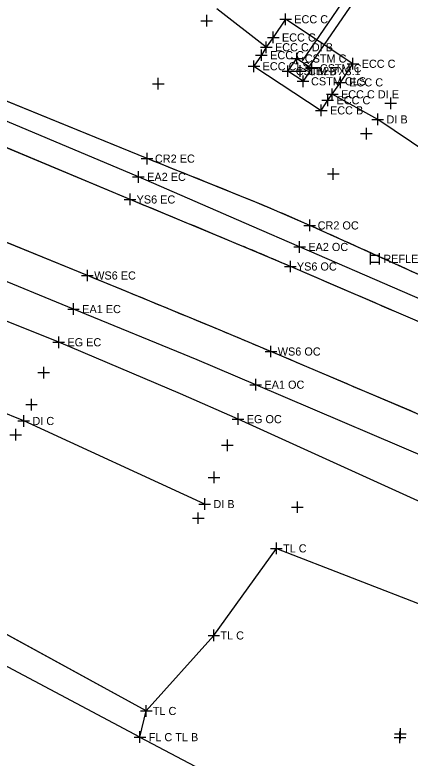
# Model space of a CAD drawing. Extents: x 1324236 to 1326110, y 459090 to 460782.
# Drawn here: x 1325338.7 to 1325406.7, y 459650.5 to 459778.5 of the extents above; entities that cross this region are included whole.
import ezdxf

# ---------------------------------------------------------------- set-up
doc = ezdxf.new("R2010")
doc.units = 0
for name, color, linetype in [('DR_X_Ditch', 7, 'Continuous'), ('DR_X_Drive_Pipe', 7, 'Continuous'), ('DR_X_Paved_Gutter', 7, 'Continuous'), ('DT_X_Island', 7, 'Continuous'), ('DT_X_Terrain_Ground_Line', 7, 'Continuous'), ('DV_X_Property_Line', 7, 'Continuous'), ('PM_X_CL_Double_Solid', 7, 'Continuous'), ('PM_X_Edge_Line', 7, 'Continuous'), ('PV_X_Shoulder', 7, 'Continuous'), ('RD_X_GR_Lt', 7, 'Continuous'), ('RW_X_CL', 7, 'Continuous'), ('RW_X_Esmt_SH', 7, 'Continuous'), ('UT_X_Electric', 7, 'Continuous'), ('VG_X_Flower_Bed', 7, 'Continuous')]:
    doc.layers.add(name, color=color, linetype=linetype)

msp = doc.modelspace()

# ---------------------------------------------------------------- linework, layer by layer
at = {"layer": 'DR_X_Ditch'}
for points in [[(1325391.45, 459762.04), (1325392.57, 459763.78), (1325393.34, 459764.8), (1325394.77, 459766.86), (1325396.9, 459770.07), (1325385.3, 459777.72), (1325383.18, 459774.59), (1325381.98, 459772.9), (1325381.15, 459771.54), (1325379.85, 459769.63), (1325391.45, 459762.04)], [(1325482.64, 459692.45), (1325469.17, 459698.73), (1325469.17, 459698.73), (1325453.52, 459705.82), (1325453.52, 459705.82), (1325439.86, 459711.89), (1325439.86, 459711.89), (1325426.21, 459717.88), (1325426.21, 459717.88), (1325425.05, 459718.39), (1325425.05, 459718.39), (1325386.13, 459735.16), (1325386.13, 459735.16), (1325378.1, 459738.57), (1325378.1, 459738.57), (1325358.54, 459746.7), (1325358.54, 459746.7), (1325327.08, 459759.85)], [(1325476.07, 459679.19), (1325455.87, 459688.71), (1325455.87, 459688.71), (1325448.5, 459692.13), (1325448.5, 459692.13), (1325438.25, 459696.75), (1325438.25, 459696.75), (1325418.97, 459705.14), (1325418.97, 459705.14), (1325417.82, 459705.63), (1325417.82, 459705.63), (1325382.79, 459720.52), (1325382.79, 459720.52), (1325372.67, 459724.76), (1325372.67, 459724.76), (1325351.19, 459733.61), (1325351.19, 459733.61), (1325320.55, 459746.12)]]:
    msp.add_lwpolyline(points, dxfattribs=at)
at = {"layer": 'DR_X_Drive_Pipe'}
for p, q in [((1325381.98, 459772.9), (1325373.46, 459779.5)), ((1325401.18, 459760.48), (1325393.34, 459764.8)), ((1325434.11, 459738.18), (1325401.18, 459760.48)), ((1325340.23, 459708.56), (1325309.55, 459721.15)), ((1325371.38, 459694.26), (1325340.23, 459708.56))]:
    msp.add_line(p, q, dxfattribs=at)
at = {"layer": 'DR_X_Paved_Gutter'}
for p, q in [((1325385.3, 459777.72), (1325383.18, 459774.59)), ((1325396.9, 459770.07), (1325385.3, 459777.72)), ((1325383.18, 459774.59), (1325381.98, 459772.9)), ((1325381.98, 459772.9), (1325381.15, 459771.54)), ((1325381.15, 459771.54), (1325379.85, 459769.63)), ((1325394.77, 459766.86), (1325396.9, 459770.07)), ((1325379.85, 459769.63), (1325391.45, 459762.04)), ((1325393.34, 459764.8), (1325394.77, 459766.86)), ((1325392.57, 459763.78), (1325393.34, 459764.8)), ((1325391.45, 459762.04), (1325392.57, 459763.78))]:
    msp.add_line(p, q, dxfattribs=at)
at = {"layer": 'DT_X_Island'}
for p, q in [((1325361.46, 459753.73), (1325329.94, 459766.58)), ((1325361.32, 459658.63), (1325323.94, 459679.11))]:
    msp.add_line(p, q, dxfattribs=at)
for points in [[(1325361.32, 459658.63), (1325323.94, 459679.11), (1325296.43, 459693.93), (1325266.13, 459708.04), (1325257.3, 459711.78), (1325234.17, 459720.37), (1325205.31, 459734.58), (1325176, 459744.8), (1325161.88, 459749.12), (1325145.8, 459759.39), (1325115.06, 459766.59), (1325083.29, 459777.3), (1325053.76, 459788.35), (1325045.01, 459789.31), (1325036.49, 459787.96), (1325032.69, 459782.63)], [(1325517.92, 459683.33), (1325497.07, 459693.59), (1325497.07, 459693.59), (1325485.83, 459698.91), (1325485.83, 459698.91), (1325457.28, 459712.1), (1325457.28, 459712.1), (1325456.45, 459712.48), (1325456.45, 459712.48), (1325445.12, 459717.41), (1325445.12, 459717.41), (1325428.9, 459724.44), (1325428.9, 459724.44), (1325420.64, 459728.13), (1325420.64, 459728.13), (1325389.47, 459742.23), (1325389.47, 459742.23), (1325381.25, 459745.77), (1325381.25, 459745.77), (1325361.46, 459753.73), (1325361.46, 459753.73), (1325329.94, 459766.58)], [(1325500.31, 459650.38), (1325476.09, 459662.1), (1325476.09, 459662.1), (1325469.56, 459665.26), (1325469.56, 459665.26), (1325458.54, 459670.63), (1325458.54, 459670.63), (1325441.71, 459678.86), (1325441.71, 459678.86), (1325430.46, 459684.28), (1325430.46, 459684.28), (1325412.38, 459692.85), (1325412.38, 459692.85), (1325411.25, 459693.37), (1325411.25, 459693.37), (1325377.12, 459708.88), (1325377.12, 459708.88), (1325367.23, 459713.24), (1325367.23, 459713.24), (1325346.25, 459722.11), (1325346.25, 459722.11), (1325315.46, 459734.46)]]:
    msp.add_lwpolyline(points, dxfattribs=at)
for centre, radius, start, end in [((1324806.2, 458345.21), 1514.02, 67.67781, 68.48478), ((1325279.8, 459498.7), 267.09, 65.7565, 67.6778), ((1321015.11, 450028.58), 10653.17, 65.572485, 65.756451)]:
    msp.add_arc(centre, radius, start, end, dxfattribs=at)
at = {"layer": 'DT_X_Terrain_Ground_Line'}
for p, q in [((1325399.84, 459737.48), (1325399.84, 459735.48)), ((1325399.84, 459737.08), (1325401.44, 459737.08)), ((1325401.44, 459737.48), (1325401.44, 459735.48)), ((1325399.84, 459735.88), (1325401.44, 459735.88))]:
    msp.add_line(p, q, dxfattribs=at)
at = {"layer": 'DV_X_Property_Line'}
for p, q in [((1325384.3, 459777.72), (1325386.3, 459777.72)), ((1325385.3, 459776.72), (1325385.3, 459778.72)), ((1325383.18, 459773.59), (1325383.18, 459775.59)), ((1325381.98, 459771.9), (1325381.98, 459773.9)), ((1325382.18, 459774.59), (1325384.18, 459774.59)), ((1325380.98, 459772.9), (1325382.98, 459772.9)), ((1325381.15, 459770.54), (1325381.15, 459772.54)), ((1325380.15, 459771.54), (1325382.15, 459771.54)), ((1325387.25, 459769.97), (1325387.25, 459771.97)), ((1325379.85, 459768.63), (1325379.85, 459770.63)), ((1325386.25, 459770.97), (1325388.25, 459770.97)), ((1325389.84, 459768.28), (1325389.84, 459770.28)), ((1325395.9, 459770.07), (1325397.9, 459770.07)), ((1325396.9, 459769.06), (1325396.9, 459771.06)), ((1325378.85, 459769.63), (1325380.85, 459769.63)), ((1325384.71, 459768.79), (1325386.71, 459768.79)), ((1325385.71, 459767.79), (1325385.71, 459769.79)), ((1325388.84, 459769.28), (1325390.84, 459769.28)), ((1325388.33, 459766.04), (1325388.33, 459768.04)), ((1325394.77, 459765.86), (1325394.77, 459767.86)), ((1325387.33, 459767.04), (1325389.33, 459767.04)), ((1325393.77, 459766.86), (1325395.77, 459766.86)), ((1325392.34, 459764.8), (1325394.34, 459764.8)), ((1325392.57, 459762.78), (1325392.57, 459764.78)), ((1325393.34, 459763.8), (1325393.34, 459765.8)), ((1325391.57, 459763.78), (1325393.57, 459763.78)), ((1325391.45, 459761.04), (1325391.45, 459763.04)), ((1325390.45, 459762.04), (1325392.45, 459762.04)), ((1325359.98, 459749.59), (1325359.98, 459751.59)), ((1325358.98, 459750.59), (1325360.98, 459750.59)), ((1325387.72, 459737.52), (1325387.72, 459739.52)), ((1325386.72, 459738.52), (1325388.72, 459738.52)), ((1325347.8, 459727.83), (1325349.8, 459727.83)), ((1325348.8, 459726.83), (1325348.8, 459728.83)), ((1325346.25, 459721.11), (1325346.25, 459723.11)), ((1325345.25, 459722.11), (1325347.25, 459722.11)), ((1325380.17, 459713.81), (1325380.17, 459715.81)), ((1325379.17, 459714.81), (1325381.17, 459714.81)), ((1325377.12, 459707.88), (1325377.12, 459709.88)), ((1325376.12, 459708.88), (1325378.12, 459708.88))]:
    msp.add_line(p, q, dxfattribs=at)
at = {"layer": 'PM_X_CL_Double_Solid'}
for q in [(1325322.01, 459674.38), (1325394.18, 459636.24)]:
    msp.add_line((1325360.24, 459654.13), q, dxfattribs=at)
at = {"layer": 'PM_X_Edge_Line'}
for p, q in [((1325358.54, 459746.7), (1325327.08, 459759.85)), ((1325351.19, 459733.61), (1325320.55, 459746.12))]:
    msp.add_line(p, q, dxfattribs=at)
for centre, radius, start, end in [((1323535.3, 455331.41), 4776.92, 67.30836, 67.56239), ((1325065.4, 458990.75), 810.57, 66.69166, 67.30836), ((1207414.73, 185918.32), 298149.15, 66.6835178, 66.6916618), ((1323259.27, 454624.44), 5520.84, 67.49249, 67.73362), ((1324901.48, 458587.63), 1230.88, 66.98181, 67.49249), ((1213240.35, 195762.5), 286792.19, 66.9742062, 66.981811)]:
    msp.add_arc(centre, radius, start, end, dxfattribs=at)
at = {"layer": 'PV_X_Shoulder'}
for points in [[(1325471.17, 459701.49), (1325454.74, 459708.74), (1325454.74, 459708.74), (1325436.72, 459717.08), (1325436.72, 459717.08), (1325427.51, 459721.26), (1325427.51, 459721.26), (1325423.19, 459723.14), (1325423.19, 459723.14), (1325387.72, 459738.52), (1325387.72, 459738.52), (1325379.47, 459742.11), (1325379.47, 459742.11), (1325359.98, 459750.59), (1325359.98, 459750.59), (1325328.62, 459763.78)], [(1325472.99, 459673.66), (1325456.57, 459681.21), (1325456.57, 459681.21), (1325445.2, 459686.39), (1325445.2, 459686.39), (1325427.97, 459694.16), (1325427.97, 459694.16), (1325415.82, 459699.55), (1325415.82, 459699.55), (1325415.12, 459699.86), (1325415.12, 459699.86), (1325380.17, 459714.81), (1325380.17, 459714.81), (1325370.08, 459719.06), (1325370.08, 459719.06), (1325348.8, 459727.83), (1325348.8, 459727.83), (1325318.08, 459740.44)]]:
    msp.add_lwpolyline(points, dxfattribs=at)
at = {"layer": 'RD_X_GR_Lt'}
for p, q in [((1325372.96, 459671.64), (1325383.74, 459686.63)), ((1325383.74, 459686.63), (1325414.9, 459674.5)), ((1325361.32, 459658.63), (1325372.96, 459671.64)), ((1325360.24, 459654.13), (1325361.32, 459658.63))]:
    msp.add_line(p, q, dxfattribs=at)
at = {"layer": 'RW_X_CL'}
for p, q in [((1325371.73, 459776.46), (1325371.73, 459778.46)), ((1325370.73, 459777.46), (1325372.73, 459777.46)), ((1325386.81, 459768.8), (1325388.81, 459768.8)), ((1325387.81, 459767.8), (1325387.81, 459769.8)), ((1325363.38, 459765.61), (1325363.38, 459767.61)), ((1325362.38, 459766.61), (1325364.38, 459766.61)), ((1325403.42, 459762.26), (1325403.42, 459764.26)), ((1325402.42, 459763.26), (1325404.42, 459763.26)), ((1325399.21, 459757.04), (1325399.21, 459759.04)), ((1325398.21, 459758.04), (1325400.21, 459758.04)), ((1325361.46, 459752.73), (1325361.46, 459754.73)), ((1325360.46, 459753.73), (1325362.46, 459753.73)), ((1325393.51, 459750.1), (1325393.51, 459752.1)), ((1325392.51, 459751.1), (1325394.51, 459751.1)), ((1325358.54, 459745.7), (1325358.54, 459747.7)), ((1325357.54, 459746.7), (1325359.54, 459746.7)), ((1325389.47, 459741.23), (1325389.47, 459743.23)), ((1325388.47, 459742.23), (1325390.47, 459742.23)), ((1325386.13, 459734.16), (1325386.13, 459736.16)), ((1325351.19, 459732.61), (1325351.19, 459734.61)), ((1325385.13, 459735.16), (1325387.13, 459735.16)), ((1325350.19, 459733.61), (1325352.19, 459733.61)), ((1325382.79, 459719.52), (1325382.79, 459721.52)), ((1325381.79, 459720.52), (1325383.79, 459720.52)), ((1325343.69, 459715.9), (1325343.69, 459717.9)), ((1325342.69, 459716.9), (1325344.69, 459716.9)), ((1325341.57, 459710.37), (1325341.57, 459712.37)), ((1325340.57, 459711.37), (1325342.57, 459711.37)), ((1325338.85, 459705.19), (1325338.85, 459707.19)), ((1325337.85, 459706.19), (1325339.85, 459706.19)), ((1325375.3, 459703.39), (1325375.3, 459705.39)), ((1325374.3, 459704.39), (1325376.3, 459704.39)), ((1325373, 459697.84), (1325373, 459699.84)), ((1325372, 459698.84), (1325374, 459698.84)), ((1325387.35, 459692.72), (1325387.35, 459694.72)), ((1325386.35, 459693.72), (1325388.35, 459693.72)), ((1325369.28, 459691.83), (1325371.28, 459691.83)), ((1325370.28, 459690.83), (1325370.28, 459692.83)), ((1325404.07, 459654.69), (1325406.07, 459654.69)), ((1325404.99, 459653.08), (1325404.99, 459655.08)), ((1325405.07, 459653.69), (1325405.07, 459655.69)), ((1325403.99, 459654.08), (1325405.99, 459654.08))]:
    msp.add_line(p, q, dxfattribs=at)
at = {"layer": 'RW_X_Esmt_SH'}
for p, q in [((1325401.18, 459759.48), (1325401.18, 459761.48)), ((1325400.18, 459760.48), (1325402.18, 459760.48)), ((1325339.23, 459708.56), (1325341.23, 459708.56)), ((1325340.23, 459707.56), (1325340.23, 459709.56)), ((1325371.38, 459693.26), (1325371.38, 459695.26)), ((1325370.38, 459694.26), (1325372.38, 459694.26)), ((1325383.74, 459685.63), (1325383.74, 459687.63)), ((1325382.74, 459686.63), (1325384.74, 459686.63)), ((1325372.96, 459670.64), (1325372.96, 459672.64)), ((1325371.96, 459671.64), (1325373.96, 459671.64)), ((1325360.32, 459658.63), (1325362.32, 459658.63)), ((1325361.32, 459657.63), (1325361.32, 459659.63)), ((1325360.24, 459653.13), (1325360.24, 459655.13)), ((1325359.24, 459654.13), (1325361.24, 459654.13))]:
    msp.add_line(p, q, dxfattribs=at)
at = {"layer": 'UT_X_Electric'}
for p, q in [((1325385.71, 459768.79), (1325387.25, 459770.97)), ((1325387.25, 459770.97), (1325389.84, 459769.28)), ((1325388.33, 459767.04), (1325385.71, 459768.79)), ((1325389.84, 459769.28), (1325388.33, 459767.04))]:
    msp.add_line(p, q, dxfattribs=at)
at = {"layer": 'VG_X_Flower_Bed'}
for p, q in [((1325388.22, 459770.57), (1325442.64, 459850.35)), ((1325443.86, 459849.49), (1325389.43, 459769.68))]:
    msp.add_line(p, q, dxfattribs=at)

# ---------------------------------------------------------------- texts
at = {"layer": 'DV_X_Property_Line'}
for s, p in [('ECC C', (1325386.8, 459777.02)), ('ECC C', (1325384.68, 459773.89)), ('ECC C DI B', (1325383.48, 459772.2)), ('ECC C', (1325382.65, 459770.84)), ('CSTM C', (1325388.61, 459770.27)), ('ECC CLS', (1325381.35, 459768.93)), ('CSTM C', (1325391.2, 459768.58)), ('ECC C', (1325398.4, 459769.36)), ('CSTM B', (1325387.06, 459768.09)), ('CSTM CLS', (1325389.69, 459766.34)), ('ECC C', (1325396.27, 459766.16)), ('ECC C DI E', (1325394.84, 459764.1)), ('ECC C', (1325394.07, 459763.08)), ('ECC B', (1325392.95, 459761.34)), ('EA2 EC', (1325361.48, 459749.89)), ('EA2 OC', (1325389.22, 459737.82)), ('EA1 EC', (1325350.3, 459727.13)), ('EG EC', (1325347.75, 459721.41)), ('EA1 OC', (1325381.67, 459714.11)), ('EG OC', (1325378.62, 459708.18))]:
    msp.add_text(s, height=1.4, dxfattribs=at).set_placement(p)
at = {"layer": 'RW_X_CL'}
for s, p in [('CB2.7X3.1', (1325389.17, 459768.1)), ('CR2 EC', (1325362.82, 459753.03)), ('YS6 EC', (1325359.66, 459746)), ('CR2 OC', (1325390.83, 459741.53)), ('YS6 OC', (1325387.25, 459734.46)), ('WS6 EC', (1325352.36, 459732.91)), ('WS6 OC', (1325383.96, 459719.82))]:
    msp.add_text(s, height=1.4, dxfattribs=at).set_placement(p)
at = {"layer": 'RW_X_Esmt_SH'}
for s, p in [('DI B', (1325402.68, 459759.78)), ('REFLECTOR', (1325402.14, 459735.78)), ('DI C', (1325341.73, 459707.86)), ('DI B', (1325372.88, 459693.56)), ('TL C', (1325384.87, 459685.93)), ('TL C', (1325374.09, 459670.94)), ('TL C', (1325362.45, 459657.93)), ('FL C TL B', (1325361.74, 459653.43))]:
    msp.add_text(s, height=1.4, dxfattribs=at).set_placement(p)

doc.saveas('drawing.dxf')
